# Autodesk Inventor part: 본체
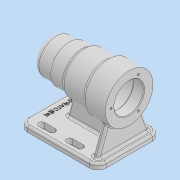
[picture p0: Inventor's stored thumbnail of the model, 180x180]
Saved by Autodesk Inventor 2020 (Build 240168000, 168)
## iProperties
Created: 2021-10
Part Number: 본체
Material: 일반
Document SubType Name: Modeling
Designer: user
Density: 1 g/cm^3
Appearance: 기본값
Author: user
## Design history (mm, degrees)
sketch "스케치1"
  geometry: L1 (0, 0)-(0, 25); L2 (0, 25)-(24, 25); L3 (24, 25)-(24, 27); L4 (24, 27)-(46, 27); L5 (46, 27)-(46, 30); L6 (46, 30)-(80, 30); L7 (80, 30)-(80, 34); L8 (80, 34)-(112, 34); L9 (112, 34)-(112, 21); L10 (112, 21)-(97, 21); L11 (97, 21)-(97, 24); L12 (97, 24)-(43, 24); L13 (43, 24)-(43, 21); L14 (43, 21)-(31, 21); L15 (31, 21)-(31, 17.5); L16 (31, 17.5)-(13, 17.5); L17 (13, 17.5)-(13, 16); L18 (13, 16)-(9, 16); L19 (9, 16)-(9, 10.5); L20 (9, 10.5)-(6, 10.5); L21 (6, 10.5)-(6, 0); L22 (6, 0)-(0, 0)
  constraints: 44 end point, 17 perpendicular, 3 vertical, 1 horizontal, 1 parallel
  dimensions: "d0" = 112 distance between parallel lines of L9 L1; "d1" = 24 distance of L1.end L2.end; "d2" = 46 distance between parallel lines of L5 L1; "d3" = 80 distance between parallel lines of L7 L1; "d5" = 34 distance between parallel lines of L22 L8; "d6" = 21 distance between parallel lines of L22 L10; "d7" = 24 distance between parallel lines of L22 L12; "d8" = 21 distance between parallel lines of L22 L14; "d9" = 17.5 distance between parallel lines of L22 L16; "d10" = 16 distance between parallel lines of L22 L18; "d11" = 10.5 distance between parallel lines of L22 L20; "d12" = 25 distance of L1.start L1.end; "d13" = 27 distance between parallel lines of L22 L4; "d14" = 30 distance between parallel lines of L22 L6; "d15" = 15 horizontal distance of L9.end L11.end; "d16" = 54 distance of L11.end L12.end; "d17" = 12 distance of L13.end L14.end; "d18" = 18 distance of L15.end L16.end; "d19" = 4 distance from line of L17.end L19; "d20" = 3 distance from line of L19.end L21
revolve "회전1" sketch "스케치1" stored, may be unused: angle "d21" = 90 deg
node "작업 평면1"
sketch "스케치2"
  geometry: L1 (0, -45)-(-112, -45); L2 (-112, -45)-(-112, 45); L3 (-112, 45)-(0, 45); L4 (0, 45)-(0, -45); L5 (0, -45)-(-112, 45); L6 (-112, -45)-(0, 45); L7 (-112, 34)-(-112, -34) reference; L8 (0, 25)-(0, -25) reference; 4 further points
  constraints: 12 end point, 4 midpoint, 2 parallel, 1 coincident, 1 collinear, 1 horizontal, 1 perpendicular
  dimensions: "d23" = 112 distance of L2.end L3.end; "d24" = 90 distance of L1.end L2.end
extrude "돌출1" join sketch "스케치2" distance "d25" = 8; taper "d26" = 0 deg
sketch "스케치3"
  geometry: L1 (27, 4)-(104, 4); L2 (104, 4)-(104, -4); L3 (104, -4)-(27, -4); L4 (27, -4)-(27, 4); L5 (27, 4)-(104, -4); L6 (104, 4)-(27, -4); L7 (112, -45)-(112, 45) reference; 3 further points
  constraints: 12 end point, 3 midpoint, 2 parallel, 1 horizontal, 1 horizontal alignment, 1 perpendicular
  dimensions: "d27" = 8 distance of L1.end L2.end; "d29" = 77 distance of L2.end L3.end; "d30" = 8 distance between parallel lines of L7 L2
extrude "돌출2" join sketch "스케치3" stored distance "d31" = 8; taper "d32" = 0 deg
node "작업 평면2"
sketch "스케치4"
  geometry: L1 (-62, 45)-(-62, -45) reference; L2 (-24.658, 23.409)-(-62, 37); L3 (-70, 45)-(-62, 45) reference; A1 r 34 centre (0, 0) between (-33.764, -4) and (-33.764, 4) reference; 1 further point
  constraints: 2 end point, 1 point on circle, 1 point on line
  dimensions: "d34" = 110 deg angle of L1 L2; "d94" = 8 distance from line of L2.end L3
feature "리브1" sketch "스케치4" dims "d35" = 1, "d36" = 8, "d37" = 0, "d38" = 0, "d39" = 1, "d40" = 1
sketch "스케치5"
  geometry: L1 (20, -33)-(35, -33); L2 (20, -37.5)-(35, -37.5); L3 (35, -28.5)-(20, -28.5); L4 (0, 45)-(0, -45) reference; L5 (60, -33)-(75, -33); L6 (60, -37.5)-(75, -37.5); L7 (75, -28.5)-(60, -28.5); L8 (20, 33)-(35, 33); L9 (20, 28.5)-(35, 28.5); L10 (35, 37.5)-(20, 37.5); L11 (60, 33)-(75, 33); L12 (60, 28.5)-(75, 28.5); L13 (75, 37.5)-(60, 37.5); A1 r 4.5 centre (20, -33) between (20, -28.5) and (20, -37.5); A2 r 4.5 centre (35, -33) between (35, -37.5) and (35, -28.5); A3 r 4.5 centre (60, -33) between (60, -28.5) and (60, -37.5); A4 r 4.5 centre (75, -33) between (75, -37.5) and (75, -28.5); A5 r 4.5 centre (20, 33) between (20, 37.5) and (20, 28.5); A6 r 4.5 centre (35, 33) between (35, 28.5) and (35, 37.5); A7 r 4.5 centre (60, 33) between (60, 37.5) and (60, 28.5); A8 r 4.5 centre (75, 33) between (75, 28.5) and (75, 37.5); 5 further points
  constraints: 32 end point, 16 point on circle, 16 tangent, 8 centre point, 4 horizontal, 4 midpoint, 4 parallel, 2 vertical alignment
  dimensions: "d41" = 15 distance of L1.start L1.end; "d42" = 9 diameter of A2; "d43" = 20 distance from line of L4 L1.start; "d44" = 15 distance of L5.start L5.end; "d45" = 9 diameter of A4; "d46" = 25 distance of L5.start L1.end; "d47" = 15 distance of L8.start L8.end; "d48" = 9 diameter of A6; "d49" = 33 vertical distance of point (27.5, -33) point (0, 0); "d50" = 33 vertical distance of point (0, 0) point (27.5, 33); "d51" = 33 vertical distance of point (0, 0) point (67.5, -33); "d52" = 15 distance of L11.start L11.end; "d53" = 9 diameter of A8; "d54" = 33 vertical distance of point (0, 0) point (67.5, 33)
extrude "돌출3" cut sketch "스케치5" distance "d55" = 50; taper "d56" = 0 deg
sketch "스케치6"
  geometry: 2 further points
  constraints: 1 horizontal alignment
  dimensions: "d57" = 26 distance of point (0, 0) point (-26, 0)
hole "구멍1" sketch "스케치6" at (-26, 0) diameter "d58" = 3.242; stored, may be unused: countersink angle "d62" = 90 deg, drill point angle "d64" = 118 deg; dims "d59" = 8, "d60" = 4, "d61" = 2, "d63" = 11
sketch "스케치7"
  geometry: L1 (0, 45)-(0, -45) reference; 3 further points
  constraints: 1 horizontal alignment, 1 midpoint, 1 other
  dimensions: "d71" = 12 distance from line of point (12, 0) L1
feature "엠보싱1" sketch "스케치7" dims "d15" = 15, "d72" = 0.5, "d73" = 0
fillet "모깎기1" dims "d74" = 12
fillet "모깎기2" dims "d75" = 3
fillet "모깎기5" dims "d78" = 8
fillet "모깎기6" dims "d79" = 3
fillet "모깎기7" dims "d80" = 0.3
fillet "모깎기8" dims "d81" = 0.3
fillet "모깎기9" dims "d82" = 3
fillet "모깎기10" dims "d83" = 3
chamfer "모따기1" distance "d84" = 1; stored, may be unused: second distance "d85" = 2, angle "d86" = 45 deg
fillet "모깎기12" dims "d88" = 3
feature "면 기울기1" dims angle "d89" = 15 deg
fillet "모깎기13" dims "d90" = 3
fillet "모깎기14" dims "d91" = 3
fillet "모깎기15" dims "d92" = 3
fillet "모깎기16" dims "d93" = 3
node "솔리드1"
mirror "미러1"
pattern_circular "원형 패턴1" dims angle "d66" = 120 deg
pattern_circular "원형 패턴2" dims angle "d69" = -120 deg
feature "A9D066F2-1C7D-4E18-AEED-F7BC21143FA4" dims "d58" = 3.242, "d59" = 8, "d60" = 4, "d61" = 2, "d62" = 90 deg, "d63" = 11, "d64" = 118 deg
other parameters: "d33" = 104
